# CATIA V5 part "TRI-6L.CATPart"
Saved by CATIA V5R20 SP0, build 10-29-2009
Part number: _TRI-6L
Definition: NONE
Nomenclature: _TRI-6L
Source: Unknown
Description: PART-_TRI-6L-DESC
Bounding box of the stored display mesh (mm): x 0 to 12, y -3 to 3, z -3 to 3
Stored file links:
  C:\Users\Utente\Desktop\IO LAVORO\3D X SITO CF\X SITO\PLASTICA\TRI\TRI-6L.CATPart
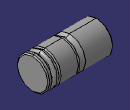
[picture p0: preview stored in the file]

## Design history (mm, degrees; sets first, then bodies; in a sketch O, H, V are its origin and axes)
Body1 "_TRI-6L" (main body)
  Solid1: solid without history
